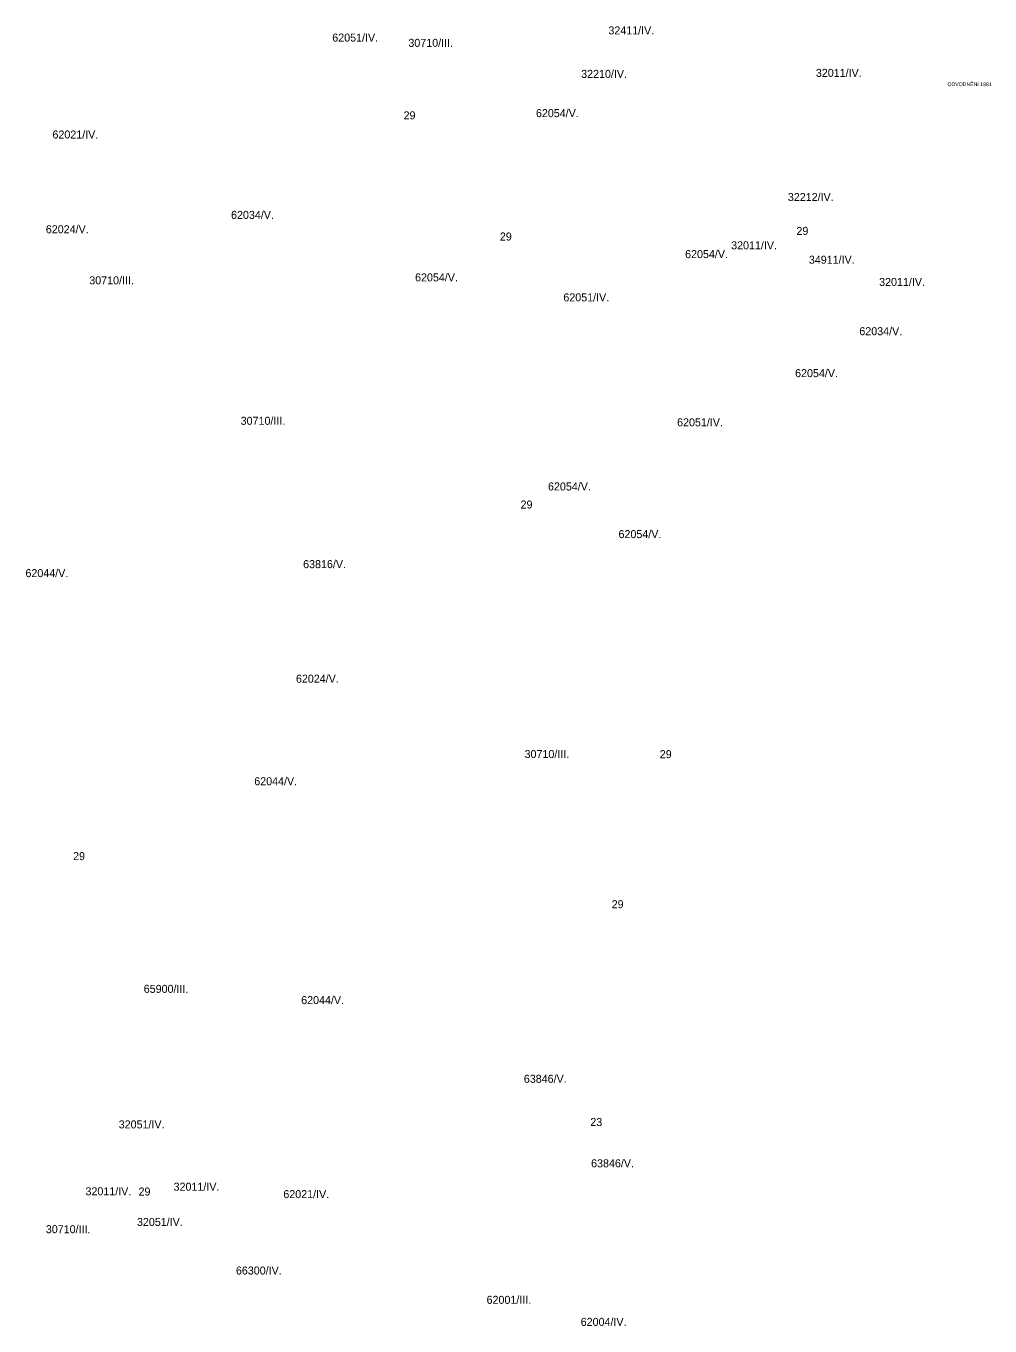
# Model space of a CAD drawing. Extents: x -521579 to -516881, y -1190081 to -1185166.
# Drawn here: x -519249 to -517442, y -1190081 to -1187644 of the extents above; entities that cross this region are included whole.
import ezdxf

# ---------------------------------------------------------------- set-up
doc = ezdxf.new("R2010")
doc.units = 0
doc.layers.add('BPEJ_s', color=7, linetype='Continuous')
doc.layers.add('odvodneni_s', color=7, linetype='Continuous')

msp = doc.modelspace()

# ---------------------------------------------------------------- texts
at = {"layer": 'BPEJ_s'}
for s, height, p in [('32411/IV.', 15, (-518157.3, -1187659.7)), ('62051/IV.', 15, (-518674.9, -1187673.2)), ('30710/III.', 15, (-518532.2, -1187683)), ('32210/IV.', 15, (-518208.3, -1187741.2)), ('32011/IV.', 15, (-517768.4, -1187739.3)), ('29', 15, (-518541.2, -1187818.9)), ('62054/V.', 15, (-518293.1, -1187814.8)), ('62021/IV.', 15, (-519199.4, -1187854.8)), ('32212/IV.', 15, (-517820.9, -1187972)), ('62034/V.', 15, (-518864.6, -1188005.5)), ('62024/V.', 15, (-519211.8, -1188032.4)), ('29', 15, (-518360.7, -1188046)), ('29', 15, (-517804.8, -1188035.5)), ('62054/V.', 15, (-518013.5, -1188079)), ('32011/IV.', 15, (-517927.2, -1188062.5)), ('34911/IV.', 15, (-517781.5, -1188089.5)), ('30710/III.', 15, (-519130.4, -1188128.1)), ('62054/V.', 15, (-518519.7, -1188122.6)), ('32011/IV.', 15, (-517649.8, -1188131.2)), ('62051/IV.', 15, (-518241.7, -1188160.1)), ('62034/V.', 15, (-517686.9, -1188223.5)), ('62054/V.', 15, (-517807.3, -1188302.1)), ('30710/III.', 15, (-518846.6, -1188391.4)), ('62051/IV.', 15, (-518028.5, -1188394.3)), ('62054/V.', 15, (-518270.5, -1188514.5)), ('29', 15, (-518321.9, -1188548.3)), ('62054/V.', 15, (-518138.3, -1188603.8)), ('63816/V.', 15, (-518729.5, -1188660.1)), ('62044/V.', 15, (-519250, -1188676.9)), ('62024/V.', 15, (-518743, -1188874.8)), ('30710/III.', 15, (-518314.4, -1189016)), ('29', 15, (-518061, -1189016.3)), ('62044/V.', 15, (-518821.1, -1189067)), ('29', 15, (-519160.7, -1189207.3)), ('29', 15, (-518151.1, -1189297.5)), ('65900/III.', 15, (-519028.3, -1189456.1)), ('62044/V.', 15, (-518733.2, -1189477.2)), ('29', 0.0647, (-518263, -1189457.1)), ('63846/V.', 15, (-518315.8, -1189624.7)), ('32051/IV.', 15, (-519075.2, -1189710.2)), ('23', 15, (-518191.2, -1189705.7)), ('63846/V.', 15, (-518189.7, -1189783.1)), ('32011/IV.', 15, (-519137.5, -1189835.6)), ('29', 15, (-519038, -1189836)), ('32011/IV.', 15, (-518972.3, -1189827)), ('62021/IV.', 15, (-518766.6, -1189840.9)), ('30710/III.', 15, (-519211.8, -1189906.6)), ('32051/IV.', 15, (-519041, -1189893)), ('66300/IV.', 15, (-518855.5, -1189984.1)), ('62001/III.', 15, (-518385.6, -1190039)), ('62004/IV.', 15, (-518209.2, -1190080.3))]:
    msp.add_text(s, height=height, dxfattribs=at).set_placement(p)
at = {"layer": 'odvodneni_s'}
msp.add_text('ODVODNĚNí 1981', height=7, dxfattribs=at).set_placement((-517521.6, -1187756.7))

doc.saveas('drawing.dxf')
